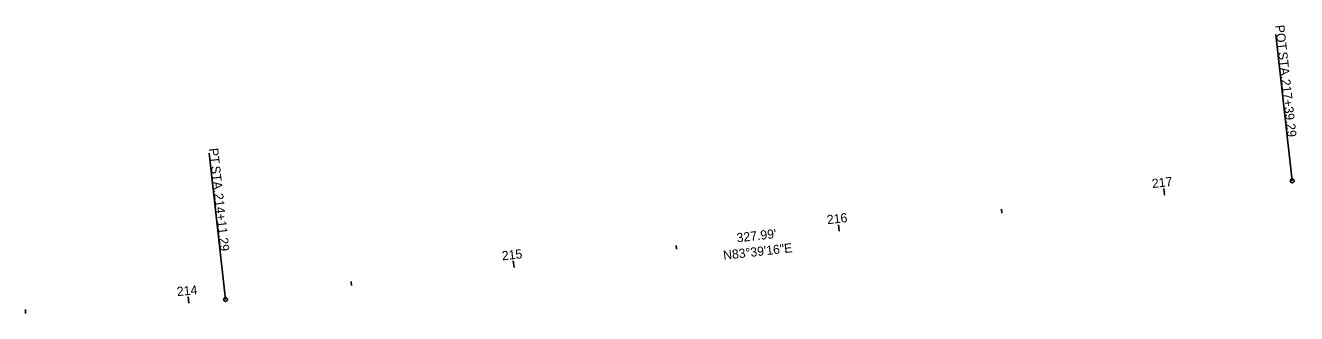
# Model space of a CAD drawing. Extents: x 1600023 to 1602131, y 285824 to 287284.
# Drawn here: x 1601716.5 to 1602105, y 286724.5 to 286812.6 of the extents above; entities that cross this region are included whole.
import ezdxf

# ---------------------------------------------------------------- set-up
doc = ezdxf.new("R2010")
doc.units = 0
for name, color, linetype in [('_CIVIL_CONSTRUCTION', 7, 'Continuous'), ('GE_P_Alignment', 7, 'Continuous'), ('PF_P_Grade_Line', 7, 'Continuous'), ('SC_Scratch6', 7, 'Continuous')]:
    doc.layers.add(name, color=color, linetype=linetype)

msp = doc.modelspace()

# ---------------------------------------------------------------- linework, layer by layer
at = {"layer": '_CIVIL_CONSTRUCTION'}
for p, q in [((1602103.63, 286765.08), (1602098.66, 286809.8)), ((1601777.65, 286728.82), (1601772.68, 286773.55))]:
    msp.add_line(p, q, dxfattribs=at)
for centre in [(1602103.63, 286765.08), (1601777.65, 286728.82)]:
    msp.add_circle(centre, 0.6, dxfattribs=at)
at = {"layer": 'SC_Scratch6'}
for p, q in [((1602064.59, 286760.73), (1602064.37, 286762.72)), ((1602014.89, 286755.21), (1602014.76, 286756.4)), ((1601965.2, 286749.68), (1601964.98, 286751.67)), ((1601915.51, 286744.16), (1601915.37, 286745.35)), ((1601865.81, 286738.63), (1601865.59, 286740.62)), ((1601816.12, 286733.1), (1601815.99, 286734.3)), ((1601766.42, 286727.66), (1601766.22, 286729.65)), ((1601716.53, 286724.5), (1601716.49, 286725.7))]:
    msp.add_line(p, q, dxfattribs=at)

# ---------------------------------------------------------------- texts
at = {"layer": '_CIVIL_CONSTRUCTION'}
for s, p in [('POT', (1602098.4, 286812.56)), (' STA. ', (1602099.19, 286805.4)), ('217+39.29', (1602100.24, 286796.01)), ('PT', (1601772.57, 286774.92)), (' STA. ', (1601773.05, 286770.54)), ('214+11.29', (1601774.1, 286761.14))]:
    msp.add_text(s, height=2.8, rotation=276.3456, dxfattribs=at).set_placement(p)
at = {"layer": 'GE_P_Alignment'}
msp.add_text('N83°39\'16"E', height=2.8, rotation=6.3456, dxfattribs=at).set_placement((1601929.88, 286740.92))
at = {"layer": 'PF_P_Grade_Line'}
msp.add_text("327.99'", height=2.8, rotation=6.3456, dxfattribs=at).set_placement((1601934, 286746.25))
at = {"layer": 'SC_Scratch6'}
for s, rotation, p in [('217', 6.3456, (1602060.92, 286762.84)), ('216', 6.3456, (1601961.59, 286751.79)), ('215', 6.3456, (1601862.25, 286740.75)), ('214', 5.4985, (1601762.92, 286729.83))]:
    msp.add_text(s, height=2.8, rotation=rotation, dxfattribs=at).set_placement(p)

doc.saveas('drawing.dxf')
